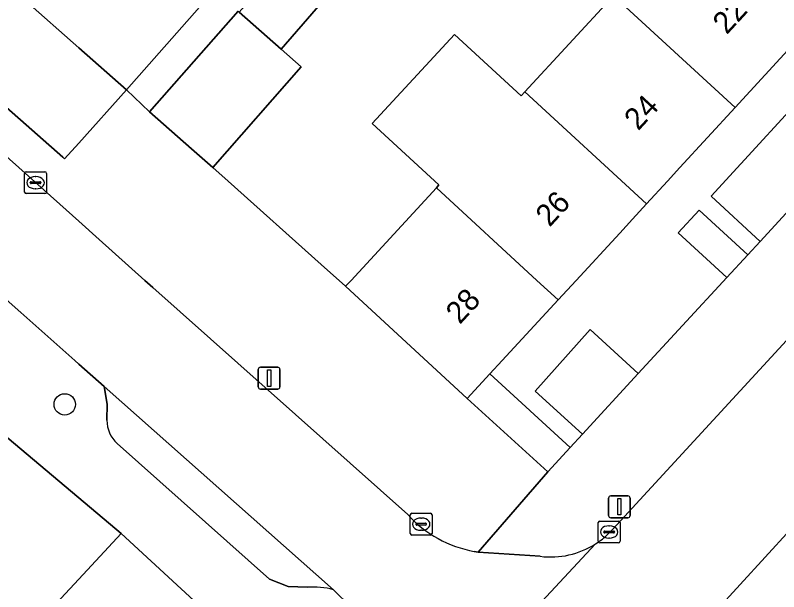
# Model space of a CAD drawing. Extents: x 162523 to 163266, y 381230 to 382050.
# Drawn here: x 162997.1 to 163032, y 381485.77 to 381512.12 of the extents above; entities that cross this region are included whole.
import ezdxf

# ---------------------------------------------------------------- set-up
doc = ezdxf.new("R2010")
doc.units = 0
for name, color, linetype in [('IMGEO_Boom', 7, 'Continuous'), ('IMGEO_Erf', 7, 'Continuous'), ('IMGEO_Groenvoorziening', 7, 'Continuous'), ('IMGEO_Kolk', 7, 'Continuous'), ('IMGEO_Lichtmast', 7, 'Continuous'), ('IMGEO_Muur', 7, 'Continuous'), ('IMGEO_Pand', 7, 'Continuous'), ('IMGEO_Pand_nummerreeks', 7, 'Continuous'), ('IMGEO_Parkeervlak_open', 7, 'Continuous'), ('IMGEO_Rijbaan_lokaal_open', 7, 'Continuous'), ('IMGEO_Voetpad_open', 7, 'Continuous')]:
    doc.layers.add(name, color=color, linetype=linetype)

msp = doc.modelspace()

# ---------------------------------------------------------------- linework, layer by layer
at = {"layer": 'IMGEO_Boom'}
msp.add_circle((162999.36, 381494.33), 0.489, dxfattribs=at)
at = {"layer": 'IMGEO_Erf'}
msp.add_lwpolyline([(162979.592, 381528.722), (162975.111, 381532.694), (162970.631, 381536.665), (162966.151, 381540.636), (162961.584, 381544.684), (162956.963, 381548.78), (162952.356, 381552.864), (162947.718, 381556.975), (162944.876, 381553.79), (162964.471, 381536.308), (162999.264, 381505.633), (162999.351, 381505.556), (163000, 381506.279), (163002.177, 381508.703), (163000, 381510.633), (162997.512, 381512.838), (162993.032, 381516.809), (162988.552, 381520.78), (162984.072, 381524.751)], close=True, dxfattribs=at)
for points in [[(163012.363, 381514.166), (163009.259, 381510.565), (163010.175, 381509.758), (163006.125, 381505.164), (163006.828, 381504.532), (163011.079, 381500.727), (163012.197, 381499.727), (163012.449, 381500), (163016.35, 381504.231), (163016.47, 381504.361), (163013.42, 381507.172), (163017.178, 381511.247), (163020.227, 381508.436), (163020.4, 381508.623), (163024.449, 381513.015)], [(163032.755, 381510.882), (163030.009, 381507.898), (163027.483, 381505.154), (163026.921, 381504.542), (163025.963, 381503.502), (163025.312, 381502.794), (163024.732, 381502.163), (163022.741, 381500), (163021.917, 381499.107), (163019.353, 381496.329), (163018.793, 381495.722), (163022.471, 381492.366), (163023.032, 381492.974), (163020.875, 381494.941), (163023.387, 381497.754), (163025.579, 381495.735), (163029.631, 381500.126), (163027.404, 381502.175), (163028.362, 381503.216), (163030.587, 381501.168), (163031.15, 381501.779), (163028.908, 381503.843), (163034.179, 381509.571)], [(162993.685, 381479.529), (162997.747, 381483.909), (163000, 381486.338), (163001.938, 381488.428), (162994.2, 381494.937)]]:
    msp.add_lwpolyline(points, dxfattribs=at)
at = {"layer": 'IMGEO_Groenvoorziening'}
for points in [[(163036.416, 381507.512), (163034.179, 381509.571), (163028.908, 381503.843), (163031.15, 381501.779)], [(163028.362, 381503.216), (163027.404, 381502.175), (163029.631, 381500.126), (163030.587, 381501.168)], [(163025.579, 381495.735), (163023.387, 381497.754), (163020.875, 381494.941), (163023.032, 381492.974)], [(163022.471, 381492.366), (163018.793, 381495.722), (163017.754, 381494.597), (163021.443, 381491.253)]]:
    msp.add_lwpolyline(points, close=True, dxfattribs=at)
at = {"layer": 'IMGEO_Kolk'}
for p, q in [((162997.525, 381504.038), (162997.525, 381504.89)), ((162997.6, 381504.964), (162998.452, 381504.964)), ((162998.526, 381504.89), (162998.526, 381504.038)), ((162998.013, 381504.744), (162998.038, 381504.744)), ((162997.784, 381504.458), (162997.784, 381504.47)), ((162998.222, 381504.421), (162997.824, 381504.421)), ((162997.827, 381504.507), (162998.225, 381504.507)), ((162998.036, 381504.184), (162998.011, 381504.184)), ((162998.268, 381504.47), (162998.268, 381504.458)), ((162998.452, 381503.964), (162997.6, 381503.964)), ((163015.156, 381488.428), (163015.156, 381489.28)), ((163015.231, 381489.354), (163016.083, 381489.354)), ((163016.157, 381489.28), (163016.157, 381488.428)), ((163015.415, 381488.848), (163015.415, 381488.86)), ((163015.458, 381488.897), (163015.856, 381488.897)), ((163015.644, 381489.134), (163015.669, 381489.134)), ((163015.899, 381488.86), (163015.899, 381488.848)), ((163023.751, 381488.071), (163023.751, 381488.923)), ((163023.826, 381488.997), (163024.678, 381488.997)), ((163024.752, 381488.923), (163024.752, 381488.071)), ((163015.853, 381488.811), (163015.455, 381488.811)), ((163015.667, 381488.574), (163015.642, 381488.574)), ((163024.01, 381488.491), (163024.01, 381488.503)), ((163024.053, 381488.54), (163024.451, 381488.54)), ((163024.239, 381488.777), (163024.264, 381488.777)), ((163024.494, 381488.503), (163024.494, 381488.491)), ((163016.083, 381488.354), (163015.231, 381488.354)), ((163024.448, 381488.454), (163024.05, 381488.454)), ((163024.262, 381488.217), (163024.237, 381488.217)), ((163024.678, 381487.997), (163023.826, 381487.997))]:
    msp.add_line(p, q, dxfattribs=at)
for points in [[(162997.525, 381504.038), (162997.525, 381504.89)], [(162997.6, 381504.964), (162998.452, 381504.964)], [(162998.526, 381504.89), (162998.526, 381504.038)], [(162998.452, 381503.964), (162997.6, 381503.964)], [(163015.156, 381488.428), (163015.156, 381489.28)], [(163015.231, 381489.354), (163016.083, 381489.354)], [(163016.157, 381489.28), (163016.157, 381488.428)], [(163023.751, 381488.071), (163023.751, 381488.923)], [(163023.826, 381488.997), (163024.678, 381488.997)], [(163024.752, 381488.923), (163024.752, 381488.071)], [(163016.083, 381488.354), (163015.231, 381488.354)], [(163024.678, 381487.997), (163023.826, 381487.997)]]:
    msp.add_lwpolyline(points, dxfattribs=at)
for centre, radius, start, end in [((162997.602, 381504.888), 0.0765, 91.552, 178.448), ((162997.602, 381504.888), 0.0765, 91.552, 178.448), ((162998.45, 381504.888), 0.0765, 1.552, 88.448), ((162998.45, 381504.888), 0.0765, 1.552, 88.448), ((162997.824, 381504.467), 0.0403, 85.8775, 175.7526), ((162997.821, 381504.457), 0.0366, 178.938, 274.7102), ((162998.225, 381504.464), 0.043, 264.8664, 352.4533), ((162998.229, 381504.469), 0.0386, 1.7309, 96.639), ((162997.602, 381504.04), 0.0765, 181.552, 268.448), ((162997.602, 381504.04), 0.0765, 181.552, 268.448), ((162998.45, 381504.04), 0.0765, 271.552, 358.448), ((162998.45, 381504.04), 0.0765, 271.552, 358.448), ((163015.233, 381489.278), 0.0765, 91.552, 178.448), ((163015.233, 381489.278), 0.0765, 91.552, 178.448), ((163016.081, 381489.278), 0.0765, 1.552, 88.448), ((163016.081, 381489.278), 0.0765, 1.552, 88.448), ((163015.455, 381488.857), 0.0403, 85.8775, 175.7526), ((163015.452, 381488.847), 0.0366, 178.938, 274.7102), ((163015.856, 381488.854), 0.043, 264.8664, 352.4533), ((163015.86, 381488.859), 0.0386, 1.7309, 96.639), ((163023.828, 381488.921), 0.0765, 91.552, 178.448), ((163023.828, 381488.921), 0.0765, 91.552, 178.448), ((163024.676, 381488.921), 0.0765, 1.552, 88.448), ((163024.676, 381488.921), 0.0765, 1.552, 88.448), ((163024.05, 381488.5), 0.0403, 85.8775, 175.7526), ((163024.047, 381488.49), 0.0366, 178.938, 274.7102), ((163024.451, 381488.497), 0.043, 264.8664, 352.4533), ((163024.455, 381488.502), 0.0386, 1.7309, 96.639), ((163015.233, 381488.43), 0.0765, 181.552, 268.448), ((163015.233, 381488.43), 0.0765, 181.552, 268.448), ((163016.081, 381488.43), 0.0765, 271.552, 358.448), ((163016.081, 381488.43), 0.0765, 271.552, 358.448), ((163023.828, 381488.073), 0.0765, 181.552, 268.448), ((163023.828, 381488.073), 0.0765, 181.552, 268.448), ((163024.676, 381488.073), 0.0765, 271.552, 358.448), ((163024.676, 381488.073), 0.0765, 271.552, 358.448)]:
    msp.add_arc(centre, radius, start, end, dxfattribs=at)
for centre, major_axis, ratio, start_param, end_param in [((162998.012, 381504.464), (-0.387, 0.002), 0.722429, 4.712389, 7.853982), ((162998.037, 381504.464), (-0.39, 0.002), 0.717154, 1.570796, 4.712389), ((163015.643, 381488.854), (-0.387, 0.002), 0.722429, 4.712389, 7.853982), ((163015.668, 381488.854), (-0.39, 0.002), 0.717154, 1.570796, 4.712389), ((163024.238, 381488.497), (-0.387, 0.002), 0.722429, 4.712389, 7.853982), ((163024.263, 381488.497), (-0.39, 0.002), 0.717154, 1.570796, 4.712389)]:
    msp.add_ellipse(centre, major_axis=major_axis, ratio=ratio, start_param=start_param, end_param=end_param, dxfattribs=at)
at = {"layer": 'IMGEO_Lichtmast'}
for p, q in [((163008.206, 381495.129), (163008.206, 381495.929)), ((163008.206, 381495.929), (163008.206, 381495.129)), ((163008.306, 381496.029), (163009.096, 381496.029)), ((163009.096, 381496.029), (163008.306, 381496.029)), ((163009.196, 381495.929), (163009.196, 381495.129)), ((163009.196, 381495.129), (163009.196, 381495.929)), ((163009.096, 381495.029), (163008.306, 381495.029)), ((163008.306, 381495.029), (163009.096, 381495.029)), ((163024.221, 381489.249), (163024.221, 381490.049)), ((163024.221, 381490.049), (163024.221, 381489.249)), ((163024.321, 381490.149), (163025.111, 381490.149)), ((163025.111, 381490.149), (163024.321, 381490.149)), ((163025.211, 381490.049), (163025.211, 381489.249)), ((163025.211, 381489.249), (163025.211, 381490.049)), ((163025.111, 381489.149), (163024.321, 381489.149)), ((163024.321, 381489.149), (163025.111, 381489.149))]:
    msp.add_line(p, q, dxfattribs=at)
for points in [[(163008.626, 381495.904), (163008.776, 381495.904), (163008.776, 381495.154), (163008.626, 381495.154), (163008.626, 381495.904)], [(163024.641, 381490.024), (163024.791, 381490.024), (163024.791, 381489.274), (163024.641, 381489.274), (163024.641, 381490.024)]]:
    msp.add_lwpolyline(points, dxfattribs=at)
for centre, start, end in [((163008.306, 381495.929), 90, 180), ((163008.306, 381495.929), 90, 180), ((163009.096, 381495.929), 0, 90), ((163009.096, 381495.929), 360, 90), ((163008.306, 381495.129), 180, 270), ((163008.306, 381495.129), 180, 270), ((163009.096, 381495.129), 270, 0), ((163009.096, 381495.129), 270, 0), ((163024.321, 381490.049), 90, 180), ((163024.321, 381490.049), 90, 180), ((163025.111, 381490.049), 0, 90), ((163025.111, 381490.049), 360, 90), ((163024.321, 381489.249), 180, 270), ((163024.321, 381489.249), 180, 270), ((163025.111, 381489.249), 270, 0), ((163025.111, 381489.249), 270, 0)]:
    msp.add_arc(centre, 0.1, start, end, dxfattribs=at)
at = {"layer": 'IMGEO_Muur'}
for points in [[(163012.197, 381499.727), (163011.079, 381500.727)], [(162994.2, 381494.937), (163001.938, 381488.428)]]:
    msp.add_lwpolyline(points, dxfattribs=at)
at = {"layer": 'IMGEO_Pand'}
for points in [[(163002.131, 381518.058), (163000, 381515.649), (162997.512, 381512.838), (163000, 381510.633), (163002.177, 381508.703), (163006.789, 381513.934)], [(163028.498, 381517.407), (163024.449, 381513.015), (163030.009, 381507.898), (163032.755, 381510.882), (163033.309, 381511.485), (163034.054, 381512.294)], [(163010.44, 381515.935), (163008.005, 381513.028), (163007.332, 381512.265), (163009.259, 381510.565), (163012.363, 381514.166)], [(163020.4, 381508.623), (163025.963, 381503.502), (163026.921, 381504.542), (163027.483, 381505.154), (163030.009, 381507.898), (163024.449, 381513.015)], [(163010.175, 381509.758), (163009.259, 381510.565), (163007.332, 381512.265), (163007.29, 381512.302), (163003.24, 381507.708), (163005.155, 381506.019), (163006.125, 381505.164)], [(163020.4, 381508.623), (163020.227, 381508.436), (163017.178, 381511.247), (163013.42, 381507.172), (163016.47, 381504.361), (163016.35, 381504.231), (163020.947, 381500), (163021.917, 381499.107), (163022.741, 381500), (163024.732, 381502.163), (163025.312, 381502.794), (163025.963, 381503.502)], [(163021.917, 381499.107), (163020.947, 381500), (163016.35, 381504.231), (163012.449, 381500), (163012.197, 381499.727), (163017.754, 381494.597), (163018.793, 381495.722), (163019.353, 381496.329)], [(163003.229, 381478.83), (163006.078, 381481.914), (163006.525, 381482.398), (163007.418, 381483.364), (163001.938, 381488.428), (163000, 381486.338), (162997.747, 381483.909), (163000, 381481.822)]]:
    msp.add_lwpolyline(points, close=True, dxfattribs=at)
at = {"layer": 'IMGEO_Parkeervlak_open'}
for points in [[(163011.645, 381485.853), (163001.157, 381495.148), (163001.293, 381494.333), (163001.289, 381493.61)], [(163001.753, 381492.541), (163008.727, 381486.346), (163009.576, 381485.999), (163010.452, 381485.969)]]:
    msp.add_lwpolyline(points, dxfattribs=at)
for centre, radius, start, end in [((163002.685, 381493.581), 1.396, 178.7903, 228.1362), ((163010.731, 381482.645), 3.336, 74.0962, 94.7965)]:
    msp.add_arc(centre, radius, start, end, dxfattribs=at)
at = {"layer": 'IMGEO_Rijbaan_lokaal_open'}
for points in [[(163003.39, 381499.675), (163003.021, 381500), (163000.93, 381501.868), (163000, 381502.699), (162990.032, 381511.604), (162986.801, 381507.947), (162995.709, 381500), (162996.681, 381499.132), (162997.351, 381498.535), (162999.813, 381496.339), (163000, 381496.173), (163001.157, 381495.148), (163011.645, 381485.853), (163012.448, 381485.053)], [(163032.521, 381488.596), (163049.121, 381506.617), (163044.716, 381510.674), (163024.416, 381488.631), (163024.228, 381488.427)], [(163015.045, 381489.291), (163003.39, 381499.675)], [(163013.11, 381476.307), (163006.085, 381468.67), (163010.497, 381464.609), (163014.639, 381469.083), (163014.865, 381469.334), (163017.474, 381472.222), (163017.716, 381472.498), (163028.809, 381484.536), (163029.092, 381484.843), (163032.521, 381488.596)], [(163013.819, 381477.41), (163023.626, 381487.95)], [(163023.626, 381487.95), (163013.819, 381477.41)], [(163021.103, 381487.384), (163018.256, 381487.577), (163018.169, 381487.591), (163018.083, 381487.606)]]:
    msp.add_lwpolyline(points, dxfattribs=at)
for centre, radius, start, end in [((163019.061, 381492.951), 5.434, 222.342, 259.6289), ((163021.597, 381491.13), 3.772, 302.5482, 314.2355), ((163021.582, 381491.154), 3.8, 262.7544, 302.534)]:
    msp.add_arc(centre, radius, start, end, dxfattribs=at)
at = {"layer": 'IMGEO_Voetpad_open'}
for points in [[(162943.227, 381555.261), (162945.207, 381557.469), (162934.089, 381566.322), (162927.51, 381571.799), (162924.941, 381574.118), (162920.788, 381577.63), (162917.851, 381574.024), (162924.31, 381568.58), (162925.474, 381567.598), (162933.285, 381561.036), (162949.507, 381547.316), (162950.943, 381546.101), (162951.542, 381545.572), (162967.702, 381531.321), (162985.328, 381515.807), (162988.055, 381513.37), (162990.032, 381511.604), (163000, 381502.699), (163000.93, 381501.868), (163003.021, 381500), (163003.39, 381499.675), (163015.045, 381489.291)], [(162917.604, 381567.698), (162914.638, 381570.187), (162911.586, 381566.758), (162915.836, 381563.236), (162917.487, 381561.716), (162933.857, 381548.227), (162936.56, 381545.986), (162938.022, 381544.713), (162938.851, 381545.67), (162949.96, 381535.97), (162952.337, 381533.894), (162990.515, 381500), (162992.639, 381498.114), (162991.799, 381497.161), (162992.727, 381496.303), (162993.042, 381496.011), (162994.2, 381494.937), (163001.938, 381488.428), (163007.418, 381483.364), (163011.108, 381480.036), (163013.791, 381482.55), (163013.743, 381482.895)], [(163018.083, 381487.606), (163018.169, 381487.591), (163018.256, 381487.577), (163021.443, 381491.253), (163017.754, 381494.597), (163012.197, 381499.727), (163011.079, 381500.727), (163006.828, 381504.532), (163006.125, 381505.164), (163005.155, 381506.019), (163003.24, 381507.708), (163002.177, 381508.703), (163000, 381506.279), (162999.351, 381505.556), (162999.264, 381505.633), (162964.471, 381536.308), (162944.876, 381553.79), (162943.227, 381555.261)], [(163057.844, 381515.164), (163069.406, 381527.653), (163068.737, 381527.889), (163051.018, 381508.676), (163049.121, 381506.617), (163032.521, 381488.596), (163029.092, 381484.843), (163028.809, 381484.536)], [(163052.364, 381524.823), (163049.858, 381522.146), (163049.079, 381521.297), (163048.601, 381520.778), (163043.21, 381514.909), (163042.633, 381514.28), (163039.125, 381510.461), (163038.601, 381509.891), (163036.97, 381508.115), (163036.416, 381507.512), (163031.15, 381501.779), (163030.587, 381501.168), (163029.631, 381500.126), (163025.579, 381495.735), (163023.032, 381492.974), (163022.471, 381492.366), (163021.443, 381491.253), (163018.256, 381487.577), (163021.103, 381487.384)], [(163006.789, 381513.934), (163002.177, 381508.703), (163003.24, 381507.708), (163007.29, 381512.302)], [(163024.228, 381488.427), (163024.416, 381488.631), (163044.716, 381510.674)], [(163001.289, 381493.61), (163001.293, 381494.333), (163001.157, 381495.148), (163000, 381496.173), (162999.813, 381496.339), (162997.351, 381498.535), (162996.681, 381499.132)], [(163010.452, 381485.969), (163009.576, 381485.999), (163008.727, 381486.346), (163001.753, 381492.541)], [(163012.448, 381485.053), (163011.645, 381485.853)]]:
    msp.add_lwpolyline(points, dxfattribs=at)
for centre, radius, start, end in [((163002.685, 381493.581), 1.396, 178.7903, 228.1362), ((163019.061, 381492.951), 5.434, 222.342, 259.6289), ((163021.597, 381491.13), 3.772, 302.5482, 314.2355), ((163021.582, 381491.154), 3.8, 262.7544, 302.534), ((163010.731, 381482.645), 3.336, 74.0962, 94.7965)]:
    msp.add_arc(centre, radius, start, end, dxfattribs=at)

# ---------------------------------------------------------------- texts
at = {"layer": 'IMGEO_Pand_nummerreeks'}
for s, rotation, p in [('22', 47.3795, (163029.628, 381511.206)), ('24', 47.3795, (163025.58, 381506.807)), ('26', 47.3779, (163021.53, 381502.406)), ('28', 47.3439, (163017.423, 381497.956))]:
    msp.add_text(s, height=1, rotation=rotation, dxfattribs=at).set_placement(p)

doc.saveas('drawing.dxf')
